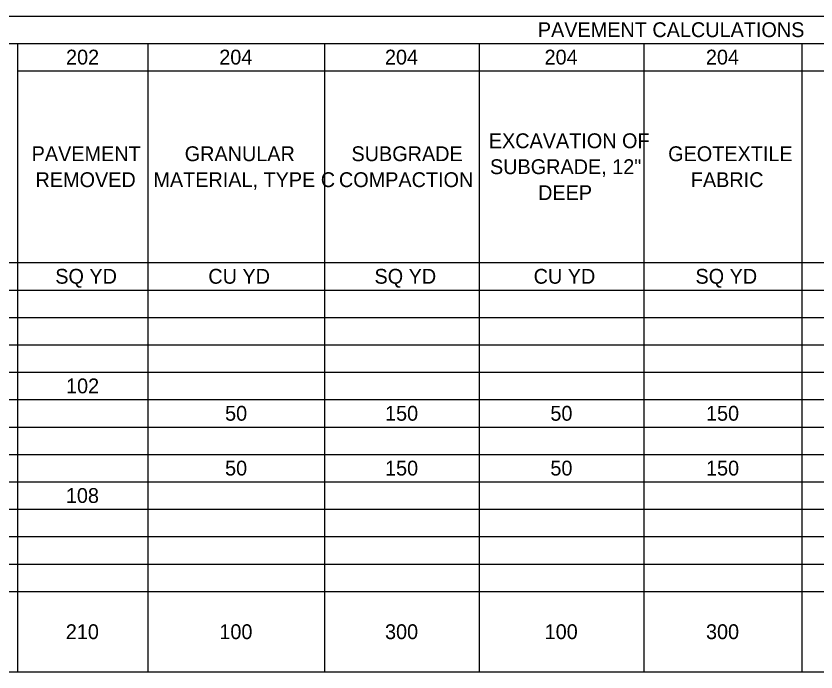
# Model space of a CAD drawing. Extents: x -27.3 to 69.3, y 0 to 30.
# Drawn here: x 49.58 to 57.14, y 15.04 to 21.23 of the extents above; entities that cross this region are included whole.
import ezdxf

# ---------------------------------------------------------------- set-up
doc = ezdxf.new("R2010")
doc.units = 0
doc.layers.add('Default', color=7, linetype='Continuous')

msp = doc.modelspace()

# ---------------------------------------------------------------- linework, layer by layer
at = {"layer": 'Default'}
for p, q in [((42.0798, 21.2276), (69.2574, 21.2276)), ((42.0798, 20.9689), (69.2574, 20.9689)), ((49.5991, 20.9689), (49.5991, 15.0364)), ((50.8278, 20.9689), (50.8278, 15.0364)), ((52.4987, 20.9689), (52.4987, 15.0364)), ((53.9567, 20.9689), (53.9567, 15.0364)), ((55.513, 20.9689), (55.513, 15.0364)), ((57.0038, 20.9689), (57.0038, 15.0364)), ((49.5991, 20.7103), (66.0793, 20.7103)), ((43.7344, 18.9001), (66.0793, 18.9001)), ((42.0798, 18.6415), (69.2574, 18.6415)), ((42.0798, 18.3829), (63.7531, 18.3829)), ((42.0798, 18.1243), (63.7531, 18.1243)), ((42.0798, 17.8657), (69.2574, 17.8657)), ((42.0798, 17.6071), (69.2574, 17.6071)), ((42.0798, 17.3485), (69.2574, 17.3485)), ((42.0798, 17.0899), (69.2574, 17.0899)), ((42.0798, 16.8313), (69.2574, 16.8313)), ((42.0798, 16.5727), (69.2574, 16.5727)), ((42.0798, 16.3141), (66.0793, 16.3141)), ((42.0798, 16.0555), (66.0793, 16.0555)), ((42.0798, 15.7969), (66.0793, 15.7969)), ((42.0798, 15.0364), (69.2574, 15.0364))]:
    msp.add_line(p, q, dxfattribs=at)

# ---------------------------------------------------------------- texts
for s, height, p in [('PAVEMENT CALCULATIONS', 0.139948, (54.5121, 21.0283)), ('202', 0.13995, (50.057, 20.7697)), ('204', 0.13995, (51.5039, 20.7697)), ('204', 0.13995, (53.0684, 20.7697)), ('204', 0.13995, (54.5755, 20.7697)), ('204', 0.13995, (56.099, 20.7697)), ('EXCAVATION OF ', 0.139948, (54.0489, 19.9802)), ('PAVEMENT ', 0.13995, (49.7324, 19.8577)), ('GRANULAR ', 0.13995, (51.1777, 19.8577)), ('SUBGRADE ', 0.13995, (52.7523, 19.8577)), ('GEOTEXTILE ', 0.139948, (55.7424, 19.8577)), ('SUBGRADE, 12" ', 0.139948, (54.06, 19.7353)), ('REMOVED', 0.13995, (49.7688, 19.6128)), ('MATERIAL, TYPE C', 0.139948, (50.8819, 19.6128)), ('COMPACTION', 0.13995, (52.6339, 19.6128)), ('FABRIC', 0.13995, (55.9563, 19.6128)), ('DEEP', 0.13995, (54.5144, 19.4904)), ('SQ YD', 0.13995, (49.9553, 18.7009)), ('CU YD', 0.13995, (51.4006, 18.7009)), ('SQ YD', 0.13995, (52.9696, 18.7009)), ('CU YD', 0.13995, (54.4722, 18.7009)), ('SQ YD', 0.13995, (56.0003, 18.7009)), ('102', 0.13995, (50.057, 17.6665)), ('50', 0.13995, (51.5587, 17.4079)), ('150', 0.13995, (53.069, 17.4079)), ('50', 0.13995, (54.6303, 17.4079)), ('150', 0.13995, (56.0997, 17.4079)), ('50', 0.13995, (51.5587, 16.8907)), ('150', 0.13995, (53.069, 16.8907)), ('50', 0.13995, (54.6303, 16.8907)), ('150', 0.13995, (56.0997, 16.8907)), ('108', 0.13995, (50.0555, 16.6321)), ('210', 0.13995, (50.0548, 15.3467)), ('100', 0.13995, (51.5046, 15.3467)), ('300', 0.13995, (53.069, 15.3467)), ('100', 0.13995, (54.5762, 15.3467)), ('300', 0.13995, (56.0997, 15.3467))]:
    msp.add_text(s, height=height, dxfattribs=at).set_placement(p)

doc.saveas('drawing.dxf')
